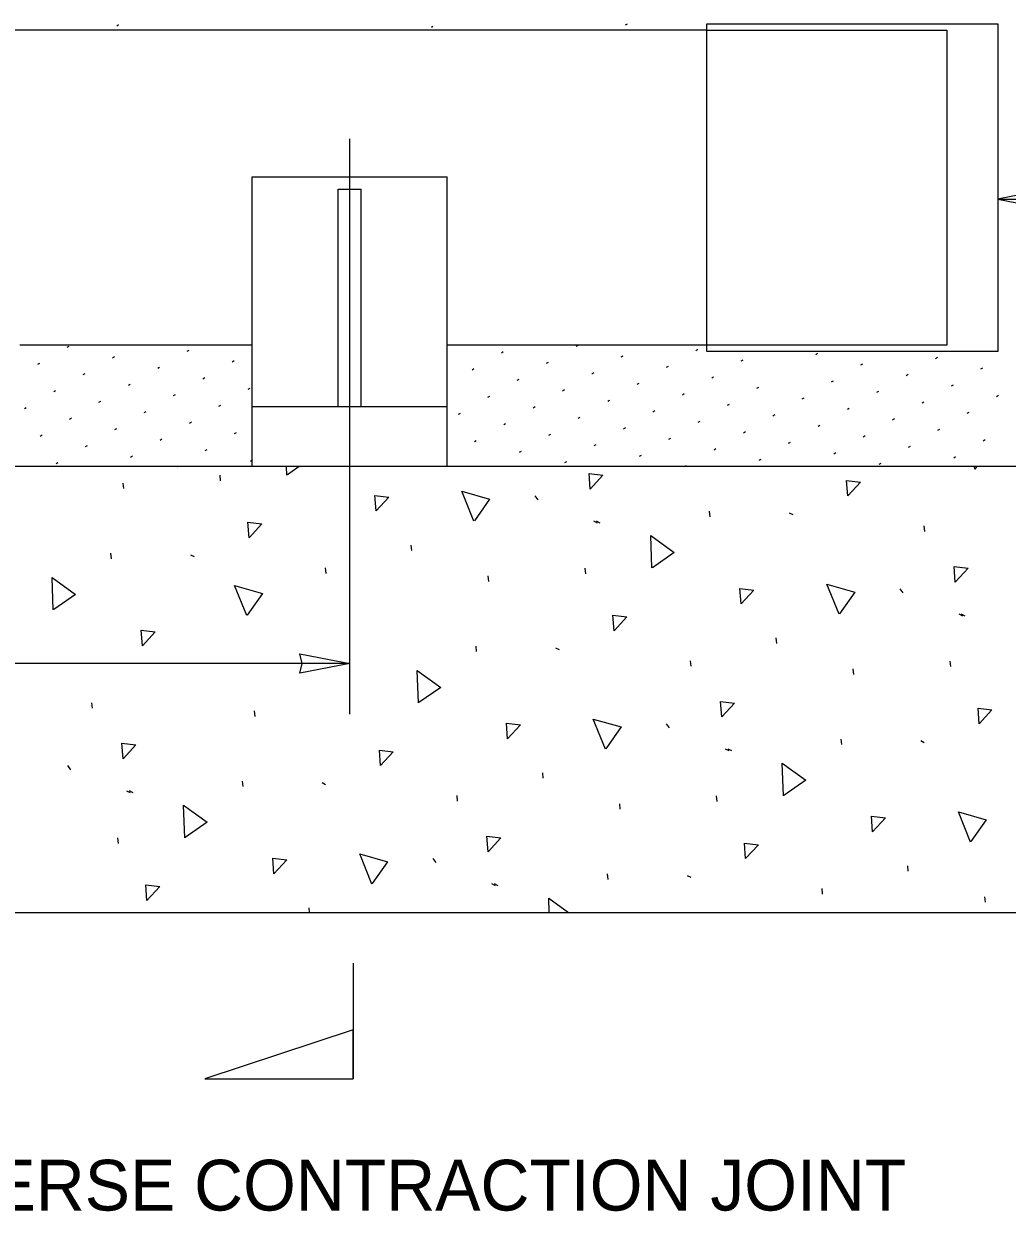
# Model space of a CAD drawing. Extents: x 99862 to 104211, y 98939 to 105076.
# Drawn here: x 101684.2 to 101994.4, y 103710.4 to 104084.9 of the extents above; entities that cross this region are included whole.
import ezdxf

# ---------------------------------------------------------------- set-up
doc = ezdxf.new("R2010")
doc.units = 0
for name, color, linetype in [('Level 1', 7, 'Continuous'), ('Level 15', 7, 'Continuous'), ('Level 2', 7, 'Continuous'), ('Level 20', 7, 'Continuous'), ('Level 3', 7, 'Continuous'), ('Level 4', 7, 'Continuous'), ('Level 6', 7, 'Continuous'), ('Level 9', 7, 'Continuous')]:
    doc.layers.add(name, color=color, linetype=linetype)

msp = doc.modelspace()

# ---------------------------------------------------------------- linework, layer by layer
at = {"layer": 'Level 1'}
msp.add_line((102063.85, 103945.23), (100698.76, 103945.23), dxfattribs=at)
msp.add_line((102063.85, 103945.23), (100698.76, 103945.23), dxfattribs=at)
msp.add_lwpolyline([(100169.63, 103804.62), (100694.77, 103804.62), (102647.84, 103804.62)], dxfattribs=at)
at = {"layer": 'Level 15'}
for p, q in [((101899.72, 104082.86), (101975.36, 104082.86)), ((101975.36, 104082.92), (101975.36, 103983.52)), ((101787.03, 103867.14), (101787.03, 104048.63)), ((101975.36, 103983.52), (101899.72, 103983.52)), ((101787.03, 103883.14), (101387.28, 103883.14))]:
    msp.add_line(p, q, dxfattribs=at)
for points in [[(101991.48, 104029.62), (102007.2, 104026.54), (102006.47, 104029.62), (102007.2, 104032.7)], [(101787.03, 103883.14), (101771.3, 103880.06), (101772.03, 103883.14), (101771.3, 103886.23)]]:
    msp.add_lwpolyline(points, close=True, dxfattribs=at)
msp.add_lwpolyline([(101991.48, 104029.62), (102057.49, 104029.62), (102057.49, 104029.62)], dxfattribs=at)
at = {"layer": 'Level 2'}
for p, q in [((101899.72, 104082.86), (101399.29, 104082.86)), ((101744.45, 103983.52), (101682.95, 103983.52)), ((101756.28, 103983.52), (101744.45, 103983.52)), ((101899.72, 103983.52), (101817.6, 103983.52))]:
    msp.add_line(p, q, dxfattribs=at)
at = {"layer": 'Level 3'}
for p, q in [((101713.55, 104084.29), (101714.15, 104084.64)), ((101874.03, 104084.57), (101874.63, 104084.92)), ((101812.79, 104083.85), (101813.3, 104084.14)), ((101697.94, 103982.9), (101698.55, 103983.25)), ((101858.42, 103983.18), (101859.03, 103983.53)), ((101712.21, 103979.59), (101712.82, 103979.94)), ((101735.74, 103981.63), (101736.35, 103981.98)), ((101834.89, 103981.14), (101835.49, 103981.49)), ((101872.69, 103979.87), (101873.3, 103980.22)), ((101896.22, 103981.91), (101896.83, 103982.26)), ((101934.03, 103980.64), (101934.63, 103980.99)), ((101971.83, 103979.37), (101972.44, 103979.72)), ((101688.67, 103977.55), (101689.28, 103977.9)), ((101726.48, 103976.28), (101727.08, 103976.63)), ((101750.01, 103978.32), (101750.62, 103978.67)), ((101825.62, 103975.79), (101826.22, 103976.14)), ((101849.15, 103977.83), (101849.76, 103978.18)), ((101886.96, 103976.56), (101887.56, 103976.91)), ((101910.49, 103978.6), (101911.1, 103978.95)), ((101948.3, 103977.33), (101948.9, 103977.68)), ((101986.1, 103976.06), (101986.7, 103976.41)), ((101702.94, 103974.24), (101703.55, 103974.59)), ((101740.74, 103972.97), (101741.35, 103973.32)), ((101839.89, 103972.48), (101840.49, 103972.83)), ((101863.42, 103974.52), (101864.03, 103974.87)), ((101901.22, 103973.25), (101901.83, 103973.6)), ((101939.03, 103971.98), (101939.63, 103972.33)), ((101962.56, 103974.02), (101963.17, 103974.37)), ((101693.67, 103968.89), (101694.28, 103969.24)), ((101717.21, 103970.93), (101717.82, 103971.28)), ((101755.01, 103969.66), (101755.62, 103970.01)), ((101854.15, 103969.17), (101854.76, 103969.52)), ((101877.69, 103971.21), (101878.3, 103971.56)), ((101891.96, 103967.9), (101892.56, 103968.25)), ((101915.49, 103969.94), (101916.1, 103970.29)), ((101953.3, 103968.67), (101953.9, 103969.02)), ((101976.83, 103970.71), (101977.44, 103971.06)), ((101707.94, 103965.58), (101708.55, 103965.93)), ((101731.48, 103967.62), (101732.08, 103967.97)), ((101745.74, 103964.31), (101746.35, 103964.66)), ((101830.62, 103967.13), (101831.22, 103967.48)), ((101868.42, 103965.86), (101869.03, 103966.21)), ((101906.22, 103964.59), (101906.83, 103964.94)), ((101929.76, 103966.63), (101930.37, 103966.98)), ((101967.56, 103965.36), (101968.17, 103965.71)), ((101991.1, 103967.4), (101991.7, 103967.75)), ((101684.41, 103963.54), (101685.01, 103963.89)), ((101698.67, 103960.23), (101699.28, 103960.58)), ((101722.21, 103962.27), (101722.82, 103962.62)), ((101821.35, 103961.78), (101821.96, 103962.13)), ((101844.89, 103963.82), (101845.49, 103964.17)), ((101859.15, 103960.51), (101859.76, 103960.86)), ((101882.69, 103962.55), (101883.3, 103962.9)), ((101920.49, 103961.28), (101921.1, 103961.63)), ((101944.03, 103963.32), (101944.63, 103963.67)), ((101981.83, 103962.05), (101982.44, 103962.4)), ((101712.94, 103956.92), (101713.55, 103957.27)), ((101736.48, 103958.96), (101737.08, 103959.31)), ((101835.62, 103958.47), (101836.22, 103958.82)), ((101873.42, 103957.2), (101874.03, 103957.55)), ((101896.96, 103959.24), (101897.56, 103959.59)), ((101934.76, 103957.97), (101935.37, 103958.32)), ((101958.3, 103960.01), (101958.9, 103960.36)), ((101972.56, 103956.7), (101973.17, 103957.05)), ((101689.41, 103954.88), (101690.01, 103955.23)), ((101727.21, 103953.61), (101727.82, 103953.96)), ((101750.74, 103955.65), (101751.35, 103956)), ((101826.35, 103953.12), (101826.96, 103953.47)), ((101849.89, 103955.16), (101850.49, 103955.51)), ((101887.69, 103953.89), (101888.3, 103954.24)), ((101911.22, 103955.93), (101911.83, 103956.28)), ((101949.03, 103954.66), (101949.63, 103955.01)), ((101986.83, 103953.39), (101987.44, 103953.74)), ((101703.67, 103951.57), (101704.28, 103951.92)), ((101741.48, 103950.3), (101742.08, 103950.65)), ((101840.62, 103949.81), (101841.22, 103950.16)), ((101864.15, 103951.85), (101864.76, 103952.2)), ((101901.96, 103950.58), (101902.56, 103950.93)), ((101925.49, 103952.62), (101926.1, 103952.97)), ((101939.76, 103949.31), (101940.37, 103949.66)), ((101963.3, 103951.35), (101963.9, 103951.7)), ((101694.41, 103946.22), (101695.01, 103946.57)), ((101717.94, 103948.26), (101718.55, 103948.61)), ((101755.74, 103946.99), (101756.35, 103947.34)), ((101854.89, 103946.5), (101855.49, 103946.85)), ((101878.42, 103948.54), (101879.03, 103948.89)), ((101916.22, 103947.27), (101916.83, 103947.62)), ((101954.03, 103946), (101954.63, 103946.35)), ((101977.56, 103948.04), (101978.17, 103948.39)), ((101732.69, 103945.23), (101732.82, 103945.3)), ((101892.69, 103945.23), (101893.3, 103945.58))]:
    msp.add_line(p, q, dxfattribs=at)
at = {"layer": 'Level 4'}
for p, q in [((101746.32, 103940.77), (101746.14, 103942.5)), ((101715.74, 103938.31), (101715.56, 103940.05)), ((101845.4, 103936.01), (101846.36, 103934.72)), ((101900.75, 103929.41), (101900.56, 103931.15)), ((101925.65, 103930.67), (101926.8, 103930.1)), ((101863.97, 103928.1), (101865.12, 103927.53)), ((101864.79, 103928.1), (101865.94, 103927.53)), ((101968.42, 103924.8), (101968.24, 103926.54)), ((101806.6, 103918.76), (101806.42, 103920.5)), ((101711.91, 103916.18), (101711.73, 103917.92)), ((101736.82, 103917.44), (101737.97, 103916.87)), ((101779.58, 103911.57), (101779.4, 103913.31)), ((101861.48, 103911.45), (101861.29, 103913.19)), ((101830.9, 103909), (101830.72, 103910.74)), ((101960.56, 103906.7), (101961.51, 103905.41)), ((101979.13, 103898.79), (101980.28, 103898.22)), ((101979.95, 103898.79), (101981.1, 103898.22)), ((101921.76, 103889.45), (101921.58, 103891.19)), ((101827.07, 103886.87), (101826.88, 103888.61)), ((101851.98, 103888.13), (101853.13, 103887.56)), ((101894.74, 103882.26), (101894.56, 103884)), ((101976.64, 103882.14), (101976.45, 103883.88)), ((101946.06, 103879.69), (101945.88, 103881.43)), ((101705.91, 103869.03), (101705.72, 103870.77)), ((101757.22, 103866.47), (101757.04, 103868.21)), ((101886.88, 103864.16), (101887.84, 103862.87)), ((101905.45, 103856.25), (101906.6, 103855.68)), ((101906.27, 103856.25), (101907.42, 103855.68)), ((101942.23, 103857.56), (101942.04, 103859.3)), ((101967.14, 103858.82), (101968.28, 103858.25)), ((101698.05, 103850.94), (101699, 103849.64)), ((101848.09, 103846.92), (101847.9, 103848.66)), ((101753.39, 103844.33), (101753.21, 103846.07)), ((101778.3, 103845.59), (101779.45, 103845.02)), ((101716.62, 103843.02), (101717.77, 103842.45)), ((101717.44, 103843.03), (101718.58, 103842.46)), ((101821.07, 103839.72), (101820.88, 103841.46)), ((101902.96, 103839.61), (101902.78, 103841.35)), ((101872.38, 103837.16), (101872.2, 103838.89)), ((101714.12, 103826.38), (101713.94, 103828.12)), ((101813.21, 103821.63), (101814.16, 103820.33)), ((101963.24, 103817.6), (101963.06, 103819.34)), ((101868.55, 103815.02), (101868.37, 103816.76)), ((101893.46, 103816.28), (101894.61, 103815.71)), ((101831.78, 103813.71), (101832.92, 103813.14)), ((101832.59, 103813.72), (101833.74, 103813.15)), ((101936.22, 103810.41), (101936.04, 103812.15)), ((101987.54, 103807.84), (101987.36, 103809.58)), ((101774.38, 103804.62), (101774.22, 103806.12))]:
    msp.add_line(p, q, dxfattribs=at)
for points in [[(101767.22, 103942.58), (101767.12, 103945.23)], [(101771.05, 103945.23), (101767.37, 103942.67)], [(101862.89, 103938.14), (101862.52, 103943.05), (101866.93, 103942.52), (101862.89, 103938.14)], [(101984.18, 103944.46), (101984.12, 103945.23)], [(101984.89, 103945.23), (101984.18, 103944.46)], [(101944.11, 103935.99), (101943.74, 103940.9), (101948.15, 103940.37), (101944.11, 103935.99)], [(101795.34, 103931.24), (101794.97, 103936.15), (101799.38, 103935.61), (101795.34, 103931.24)], [(101826.24, 103927.98), (101822.38, 103937.47), (101831.17, 103934.96), (101826.35, 103928.11)], [(101755.28, 103922.76), (101754.9, 103927.67), (101759.31, 103927.14), (101755.28, 103922.76)], [(101882.38, 103913.27), (101882, 103923.51), (101889.41, 103918.15), (101882.53, 103913.36)], [(101978.05, 103908.83), (101977.68, 103913.74), (101982.09, 103913.21), (101978.05, 103908.83)], [(101693.54, 103900.04), (101693.17, 103910.28), (101700.57, 103904.92), (101693.7, 103900.13)], [(101941.39, 103898.67), (101937.54, 103908.16), (101946.33, 103905.65), (101941.51, 103898.8)], [(101754.57, 103898.25), (101750.71, 103907.75), (101759.51, 103905.24), (101754.68, 103898.39)], [(101910.5, 103901.92), (101910.13, 103906.84), (101914.54, 103906.3), (101910.5, 103901.92)], [(101870.44, 103893.45), (101870.06, 103898.36), (101874.47, 103897.83), (101870.44, 103893.45)], [(101721.67, 103888.7), (101721.29, 103893.61), (101725.7, 103893.08), (101721.67, 103888.7)], [(101808.7, 103870.73), (101808.33, 103880.97), (101815.73, 103875.61), (101808.86, 103870.82)], [(101904.38, 103866.29), (101904, 103871.2), (101908.41, 103870.67), (101904.38, 103866.29)], [(101985.6, 103864.14), (101985.22, 103869.05), (101989.63, 103868.52), (101985.6, 103864.14)], [(101836.82, 103859.39), (101836.45, 103864.3), (101840.86, 103863.77), (101836.82, 103859.39)], [(101867.72, 103856.13), (101863.86, 103865.62), (101872.65, 103863.11), (101867.83, 103856.26)], [(101715.54, 103853.06), (101715.16, 103857.97), (101719.57, 103857.44), (101715.54, 103853.06)], [(101796.76, 103850.92), (101796.38, 103855.83), (101800.79, 103855.29), (101796.76, 103850.92)], [(101923.86, 103841.42), (101923.48, 103851.66), (101930.89, 103846.3), (101924.01, 103841.51)], [(101735.02, 103828.19), (101734.65, 103838.43), (101742.05, 103833.07), (101735.18, 103828.28)], [(101951.98, 103830.08), (101951.61, 103834.99), (101956.02, 103834.46), (101951.98, 103830.08)], [(101982.88, 103826.82), (101979.02, 103836.31), (101987.81, 103833.8), (101982.99, 103826.95)], [(101830.7, 103823.75), (101830.32, 103828.66), (101834.73, 103828.13), (101830.7, 103823.75)], [(101911.92, 103821.6), (101911.54, 103826.52), (101915.95, 103825.98), (101911.92, 103821.6)], [(101794.04, 103813.59), (101790.18, 103823.09), (101798.98, 103820.58), (101794.15, 103813.73)], [(101763.15, 103816.85), (101762.77, 103821.76), (101767.18, 103821.23), (101763.15, 103816.85)], [(101723.08, 103808.38), (101722.71, 103813.29), (101727.12, 103812.76), (101723.08, 103808.38)], [(101849.97, 103804.62), (101849.81, 103809.12), (101856.02, 103804.62)]]:
    msp.add_lwpolyline(points, dxfattribs=at)
at = {"layer": 'Level 6'}
for p, q in [((101899.72, 103981.54), (101899.72, 104084.89)), ((101899.72, 104084.89), (101991.48, 104084.89)), ((101991.48, 104084.89), (101991.48, 103981.54)), ((101756.28, 103945.23), (101756.28, 104036.63)), ((101756.28, 104036.63), (101817.78, 104036.63)), ((101817.78, 103945.23), (101817.78, 104036.63)), ((101783.35, 104032.75), (101790.7, 104032.75)), ((101783.35, 103964.17), (101783.35, 104032.75)), ((101790.7, 103964.17), (101790.7, 104032.75)), ((101991.48, 103981.54), (101899.72, 103981.54)), ((101756.28, 103964.17), (101817.78, 103964.17))]:
    msp.add_line(p, q, dxfattribs=at)
at = {"layer": 'Level 9'}
msp.add_line((101788.17, 103788.62), (101788.17, 103752.1), dxfattribs=at)
msp.add_lwpolyline([(101788.17, 103767.62), (101741.29, 103752.1), (101788.17, 103752.1)], close=True, dxfattribs=at)

# ---------------------------------------------------------------- texts
at = {"layer": 'Level 20'}
msp.add_text('TRANSVERSE CONTRACTION JOINT  ', height=16, dxfattribs=at).set_placement((101586.95, 103710.6))

doc.saveas('drawing.dxf')
